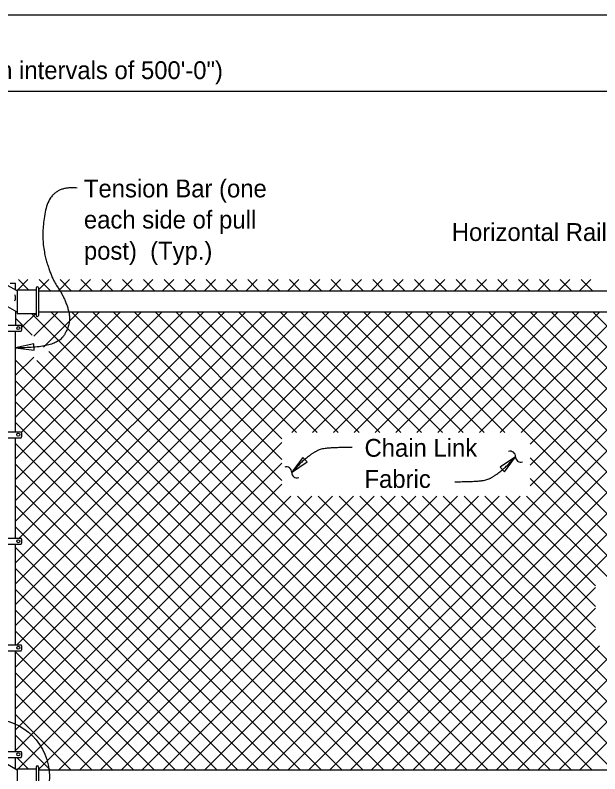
# Model space of a CAD drawing. Extents: x 110698 to 110915, y 110390 to 110472.
# Drawn here: x 110786.41 to 110793.02, y 110456.22 to 110464.8 of the extents above; entities that cross this region are included whole.
import ezdxf

# ---------------------------------------------------------------- set-up
doc = ezdxf.new("R2010")
doc.units = 0
for name, color, linetype in [('ActivePts-ConstElements', 7, 'Continuous'), ('Border', 7, 'Continuous'), ('PlotBorder_dp', 7, 'Continuous'), ('SheetBorder_dp', 7, 'Continuous'), ('TextMisc', 7, 'Continuous')]:
    doc.layers.add(name, color=color, linetype=linetype)

msp = doc.modelspace()

# ---------------------------------------------------------------- linework, layer by layer
at = {"layer": 'ActivePts-ConstElements'}
msp.add_lwpolyline([(110774.0658, 110438.856), (110815.1163, 110438.856), (110815.1163, 110464.8021), (110774.0658, 110464.8021)], close=True, dxfattribs=at)
at = {"layer": 'PlotBorder_dp'}
msp.add_line((110776.1407, 110463.9443), (110796.1408, 110463.9443), dxfattribs=at)
for points in [[(110786.4116, 110461.0428), (110786.6211, 110461.0159), (110786.6183, 110461.0864)], [(110789.5343, 110459.633), (110789.7096, 110459.7509), (110789.661, 110459.802)], [(110792.0665, 110459.8091), (110791.8912, 110459.6912), (110791.9398, 110459.64)]]:
    msp.add_lwpolyline(points, close=True, dxfattribs=at)
msp.add_circle((110786.1422, 110456.193), 0.6527, dxfattribs=at)
for centre, start, end in [((110792.0064, 110459.8118), 357.71778, 109.44499), ((110792.1255, 110459.8071), 177.71778, 289.44499), ((110789.4752, 110459.6349), 357.71778, 109.44499), ((110789.5944, 110459.6301), 177.71778, 289.44499)]:
    msp.add_arc(centre, 0.0596, start, end, dxfattribs=at)
for points in [[(110787.1072, 110462.8473), (110786.8071, 110462.8793), (110786.6917, 110462.297), (110786.8068, 110461.8427), (110786.9704, 110461.6076), (110787.0496, 110461.3212), (110786.8632, 110461.0324), (110786.4116, 110461.0428)], [(110790.2195, 110459.9146), (110789.9294, 110459.9146), (110789.7928, 110459.8698), (110789.6058, 110459.7162), (110789.5674, 110459.6586)], [(110791.3812, 110459.5273), (110791.6714, 110459.5273), (110791.808, 110459.5721), (110791.995, 110459.7257), (110792.0333, 110459.7833)]]:
    msp.add_open_spline(points, degree=2, dxfattribs=at)
at = {"layer": 'SheetBorder_dp'}
for p, q in [((110786.437, 110461.6985), (110786.5518, 110461.8133)), ((110786.4443, 110461.8133), (110786.5591, 110461.6985)), ((110786.6701, 110461.6959), (110786.7875, 110461.8133)), ((110786.68, 110461.8133), (110786.8102, 110461.6831)), ((110786.893, 110461.6831), (110787.0232, 110461.8133)), ((110786.9157, 110461.8133), (110787.0459, 110461.6831)), ((110787.1287, 110461.6831), (110787.2589, 110461.8133)), ((110787.1514, 110461.8133), (110787.2816, 110461.6831)), ((110787.3644, 110461.6831), (110787.4946, 110461.8133)), ((110787.3871, 110461.8133), (110787.5173, 110461.6831)), ((110787.6001, 110461.6831), (110787.7303, 110461.8133)), ((110787.6228, 110461.8133), (110787.753, 110461.6831)), ((110787.8358, 110461.6831), (110787.966, 110461.8133)), ((110787.8585, 110461.8133), (110787.9887, 110461.6831)), ((110788.0715, 110461.6831), (110788.2017, 110461.8133)), ((110788.0942, 110461.8133), (110788.2244, 110461.6831)), ((110788.3072, 110461.6831), (110788.4374, 110461.8133)), ((110788.3299, 110461.8133), (110788.4601, 110461.6831)), ((110788.5429, 110461.6831), (110788.6731, 110461.8133)), ((110788.5656, 110461.8133), (110788.6958, 110461.6831)), ((110788.7786, 110461.6831), (110788.9088, 110461.8133)), ((110788.8013, 110461.8133), (110788.9315, 110461.6831)), ((110789.0143, 110461.6831), (110789.1445, 110461.8133)), ((110789.0371, 110461.8133), (110789.1672, 110461.6831)), ((110789.25, 110461.6831), (110789.3802, 110461.8133)), ((110789.2728, 110461.8133), (110789.4029, 110461.6831)), ((110789.4857, 110461.6831), (110789.6159, 110461.8133)), ((110789.5085, 110461.8133), (110789.6386, 110461.6831)), ((110789.7214, 110461.6831), (110789.8516, 110461.8133)), ((110789.7442, 110461.8133), (110789.8743, 110461.6831)), ((110789.9571, 110461.6831), (110790.0873, 110461.8133)), ((110789.9799, 110461.8133), (110790.11, 110461.6831)), ((110790.1928, 110461.6831), (110790.323, 110461.8133)), ((110790.2156, 110461.8133), (110790.3457, 110461.6831)), ((110790.4285, 110461.6831), (110790.5587, 110461.8133)), ((110790.4513, 110461.8133), (110790.5814, 110461.6831)), ((110790.6642, 110461.6831), (110790.7944, 110461.8133)), ((110790.687, 110461.8133), (110790.8171, 110461.6831)), ((110790.8999, 110461.6831), (110791.0301, 110461.8133)), ((110790.9227, 110461.8133), (110791.0528, 110461.6831)), ((110791.1356, 110461.6831), (110791.2658, 110461.8133)), ((110791.1584, 110461.8133), (110791.2885, 110461.6831)), ((110791.3714, 110461.6831), (110791.5015, 110461.8133)), ((110791.3941, 110461.8133), (110791.5242, 110461.6831)), ((110791.6071, 110461.6831), (110791.7372, 110461.8133)), ((110791.6298, 110461.8133), (110791.7599, 110461.6831)), ((110791.8428, 110461.6831), (110791.9729, 110461.8133)), ((110791.8655, 110461.8133), (110791.9956, 110461.6831)), ((110792.0785, 110461.6831), (110792.2086, 110461.8133)), ((110792.1012, 110461.8133), (110792.2313, 110461.6831)), ((110792.3142, 110461.6831), (110792.4443, 110461.8133)), ((110792.3369, 110461.8133), (110792.467, 110461.6831)), ((110792.5499, 110461.6831), (110792.68, 110461.8133)), ((110792.5726, 110461.8133), (110792.7028, 110461.6831)), ((110792.7856, 110461.6831), (110792.9157, 110461.8133)), ((110792.8083, 110461.8133), (110792.9385, 110461.6831)), ((110786.4116, 110458.3733), (110789.4819, 110461.4435)), ((110786.4116, 110457.9019), (110789.9533, 110461.4435)), ((110786.4116, 110459.7875), (110788.0676, 110461.4435)), ((110786.4116, 110459.3161), (110788.539, 110461.4435)), ((110786.4116, 110460.2589), (110787.5962, 110461.4435)), ((110786.4116, 110458.1376), (110789.7176, 110461.4435)), ((110786.4116, 110458.609), (110789.2461, 110461.4435)), ((110786.4116, 110459.0804), (110788.7747, 110461.4435)), ((110786.4116, 110459.5518), (110788.3033, 110461.4435)), ((110786.4116, 110457.1948), (110790.6604, 110461.4435)), ((110786.4116, 110457.4305), (110790.4247, 110461.4435)), ((110786.4116, 110460.4946), (110787.3605, 110461.4435)), ((110786.4279, 110457.6825), (110790.189, 110461.4435)), ((110786.4543, 110458.8873), (110789.0104, 110461.4435)), ((110786.4775, 110460.0891), (110787.8319, 110461.4435)), ((110786.4835, 110461.2736), (110786.6433, 110461.4334)), ((110786.5956, 110461.4263), (110791.7555, 110456.2664)), ((110786.6182, 110461.1725), (110786.8891, 110461.4435)), ((110786.729, 110461.0477), (110787.1248, 110461.4435)), ((110786.8141, 110461.4435), (110791.9912, 110456.2664)), ((110787.0498, 110461.4435), (110792.2269, 110456.2664)), ((110787.2855, 110461.4435), (110792.4626, 110456.2664)), ((110787.5212, 110461.4435), (110789.4233, 110459.5414)), ((110787.7569, 110461.4435), (110789.4233, 110459.7771)), ((110787.9926, 110461.4435), (110789.4233, 110460.0128)), ((110788.2283, 110461.4435), (110789.5888, 110460.083)), ((110788.464, 110461.4435), (110789.8245, 110460.083)), ((110788.6997, 110461.4435), (110790.0602, 110460.083)), ((110788.9354, 110461.4435), (110790.2959, 110460.083)), ((110789.1711, 110461.4435), (110790.5316, 110460.083)), ((110789.2545, 110456.2664), (110794.4316, 110461.4435)), ((110789.4068, 110461.4435), (110790.7673, 110460.083)), ((110789.4902, 110456.2664), (110794.6673, 110461.4435)), ((110789.5356, 110460.083), (110790.8961, 110461.4435)), ((110789.6425, 110461.4435), (110791.003, 110460.083)), ((110789.7259, 110456.2664), (110794.903, 110461.4435)), ((110789.7713, 110460.083), (110791.1318, 110461.4435)), ((110789.8782, 110461.4435), (110791.2387, 110460.083)), ((110789.9616, 110456.2664), (110795.1387, 110461.4435)), ((110790.007, 110460.083), (110791.3675, 110461.4435)), ((110790.1139, 110461.4435), (110791.4744, 110460.083)), ((110790.1973, 110456.2664), (110795.3744, 110461.4435)), ((110790.2427, 110460.083), (110791.6032, 110461.4435)), ((110790.3496, 110461.4435), (110791.7101, 110460.083)), ((110790.433, 110456.2664), (110795.6114, 110461.4448)), ((110790.4784, 110460.083), (110791.8389, 110461.4435)), ((110790.5853, 110461.4435), (110791.9458, 110460.083)), ((110790.6687, 110456.2664), (110795.8286, 110461.4263)), ((110790.7141, 110460.083), (110792.0746, 110461.4435)), ((110790.821, 110461.4435), (110793.8469, 110458.4176)), ((110790.9498, 110460.083), (110792.3103, 110461.4435)), ((110791.0567, 110461.4435), (110794.0826, 110458.4176)), ((110791.1855, 110460.083), (110792.546, 110461.4435)), ((110791.2924, 110461.4435), (110794.3183, 110458.4176)), ((110791.4212, 110460.083), (110792.7817, 110461.4435)), ((110791.5281, 110461.4435), (110794.554, 110458.4176)), ((110791.6569, 110460.083), (110793.0174, 110461.4435)), ((110791.7638, 110461.4435), (110794.7897, 110458.4176)), ((110791.8926, 110460.083), (110793.2531, 110461.4435)), ((110791.9995, 110461.4435), (110795.0254, 110458.4176)), ((110792.1283, 110460.083), (110793.4888, 110461.4435)), ((110792.2315, 110459.9505), (110793.7245, 110461.4435)), ((110792.2315, 110459.4791), (110794.1959, 110461.4435)), ((110792.2315, 110459.7148), (110793.9602, 110461.4435)), ((110792.2352, 110461.4435), (110795.2611, 110458.4176)), ((110792.4709, 110461.4435), (110795.4968, 110458.4176)), ((110792.7066, 110461.4435), (110795.7325, 110458.4176)), ((110792.9423, 110461.4435), (110795.995, 110458.3909)), ((110786.4116, 110461.3745), (110786.6002, 110461.186)), ((110786.7882, 110460.9979), (110791.5198, 110456.2664)), ((110786.4116, 110460.7303), (110786.6184, 110460.9371)), ((110786.4116, 110460.9031), (110791.0484, 110456.2664)), ((110786.6513, 110460.8992), (110791.2841, 110456.2664)), ((110786.4116, 110460.6674), (110790.8127, 110456.2664)), ((110786.4116, 110460.4317), (110790.577, 110456.2664)), ((110786.4116, 110460.196), (110790.3413, 110456.2664)), ((110786.4116, 110456.9591), (110789.4233, 110459.9708)), ((110786.4116, 110459.9603), (110790.1056, 110456.2664)), ((110792.2315, 110459.7974), (110793.6112, 110458.4176)), ((110786.4116, 110456.7234), (110789.4233, 110459.7351)), ((110786.4116, 110459.7246), (110789.8699, 110456.2664)), ((110792.2315, 110459.5617), (110793.3755, 110458.4176)), ((110786.4116, 110456.4877), (110789.4233, 110459.4994)), ((110786.4116, 110459.4889), (110789.6342, 110456.2664)), ((110786.4415, 110456.2818), (110789.5253, 110459.3656)), ((110786.6701, 110456.2748), (110789.761, 110459.3656)), ((110786.8974, 110456.2664), (110789.9967, 110459.3656)), ((110787.1331, 110456.2664), (110790.2324, 110459.3656)), ((110787.3688, 110456.2664), (110790.4681, 110459.3656)), ((110787.6045, 110456.2664), (110790.7038, 110459.3656)), ((110787.8403, 110456.2664), (110790.9395, 110459.3656)), ((110788.076, 110456.2664), (110791.1752, 110459.3656)), ((110788.3117, 110456.2664), (110791.4109, 110459.3656)), ((110788.5474, 110456.2664), (110791.6466, 110459.3656)), ((110788.7831, 110456.2664), (110791.8823, 110459.3656)), ((110789.0188, 110456.2664), (110792.118, 110459.3656)), ((110789.5991, 110459.3656), (110792.6983, 110456.2664)), ((110789.8348, 110459.3656), (110792.934, 110456.2664)), ((110790.0705, 110459.3656), (110793.1697, 110456.2664)), ((110790.3062, 110459.3656), (110793.4054, 110456.2664)), ((110790.5419, 110459.3656), (110793.6411, 110456.2664)), ((110790.7776, 110459.3656), (110793.8768, 110456.2664)), ((110791.0133, 110459.3656), (110794.1125, 110456.2664)), ((110791.249, 110459.3656), (110794.3482, 110456.2664)), ((110791.4847, 110459.3656), (110792.97, 110457.8803)), ((110791.7204, 110459.3656), (110792.97, 110458.116)), ((110791.9561, 110459.3656), (110792.97, 110458.3517)), ((110792.1918, 110459.3656), (110793.1398, 110458.4176)), ((110786.4116, 110459.2532), (110789.3985, 110456.2664)), ((110786.4116, 110459.0175), (110789.1628, 110456.2664)), ((110786.4116, 110458.7818), (110788.9271, 110456.2664)), ((110786.4116, 110458.5461), (110788.6914, 110456.2664)), ((110786.4116, 110458.3104), (110788.4557, 110456.2664)), ((110790.9044, 110456.2664), (110792.97, 110458.332)), ((110791.1401, 110456.2664), (110792.97, 110458.0963)), ((110786.4116, 110458.0747), (110788.22, 110456.2664)), ((110786.4116, 110457.839), (110787.9843, 110456.2664)), ((110791.3758, 110456.2664), (110792.97, 110457.8606)), ((110791.6115, 110456.2664), (110793.0172, 110457.6721)), ((110791.8472, 110456.2664), (110793.2529, 110457.6721)), ((110792.0829, 110456.2664), (110793.4886, 110457.6721)), ((110792.3186, 110456.2664), (110793.7243, 110457.6721)), ((110792.5543, 110456.2664), (110793.96, 110457.6721)), ((110792.79, 110456.2664), (110794.1957, 110457.6721)), ((110786.4116, 110457.6033), (110787.7486, 110456.2664)), ((110786.4116, 110457.3676), (110787.5129, 110456.2664)), ((110786.4116, 110457.1319), (110787.2772, 110456.2664)), ((110786.4116, 110456.8962), (110787.0415, 110456.2664)), ((110786.4116, 110456.6605), (110786.8058, 110456.2664)), ((110786.4262, 110456.4102), (110786.5546, 110456.2818))]:
    msp.add_line(p, q, dxfattribs=at)
at = {"layer": 'TextMisc'}
for p, q in [((110786.3491, 110461.7716), (110786.4116, 110461.7716)), ((110786.4116, 110461.6941), (110786.4116, 110461.7716)), ((110786.4303, 110461.6838), (110786.3195, 110461.7452)), ((110786.4303, 110461.6985), (110786.4303, 110461.4263)), ((110786.4303, 110461.6985), (110786.6433, 110461.6985)), ((110786.6433, 110461.7181), (110786.6433, 110461.4084)), ((110786.6701, 110461.7181), (110786.6701, 110461.4084)), ((110795.6114, 110461.6831), (110786.6701, 110461.6831)), ((110786.4303, 110461.4444), (110786.2164, 110461.563)), ((110786.4116, 110461.4548), (110786.4116, 110461.2967)), ((110786.4116, 110461.4548), (110786.4116, 110461.4425)), ((110786.6433, 110461.4263), (110786.4303, 110461.4263)), ((110795.6114, 110461.4435), (110786.6701, 110461.4435)), ((110785.9851, 110461.2967), (110786.4761, 110461.2967)), ((110785.9851, 110461.2291), (110786.4754, 110461.2291)), ((110786.4116, 110460.092), (110786.4116, 110461.2291)), ((110785.9851, 110460.092), (110786.4761, 110460.092)), ((110785.9851, 110460.0244), (110786.4754, 110460.0244)), ((110786.4116, 110458.8873), (110786.4116, 110460.0244)), ((110785.9851, 110458.8873), (110786.4761, 110458.8873)), ((110785.9851, 110458.8197), (110786.4754, 110458.8197)), ((110786.4116, 110457.6825), (110786.4116, 110458.8197)), ((110785.9851, 110457.6825), (110786.4761, 110457.6825)), ((110785.9851, 110457.6149), (110786.4754, 110457.6149)), ((110786.4116, 110456.4779), (110786.4116, 110457.6149)), ((110785.9851, 110456.4779), (110786.4761, 110456.4779)), ((110785.9851, 110456.4102), (110786.4754, 110456.4102)), ((110786.4116, 110456.2774), (110786.4116, 110456.4102)), ((110786.4303, 110456.2671), (110786.3195, 110456.3284)), ((110786.4303, 110456.2818), (110786.4303, 110456.0096)), ((110786.4303, 110456.2818), (110786.6433, 110456.2818)), ((110786.6433, 110456.3014), (110786.6433, 110455.9917)), ((110786.6701, 110456.3014), (110786.6701, 110455.9917)), ((110795.6114, 110456.2664), (110786.6701, 110456.2664))]:
    msp.add_line(p, q, dxfattribs=at)
for centre, start, end in [((110786.6566, 110461.718), 0, 180), ((110786.6566, 110461.4082), 180, 0), ((110786.6566, 110456.3013), 0, 180)]:
    msp.add_arc(centre, 0.0134, start, end, dxfattribs=at)
for centre, start_param, end_param in [((110786.334, 110461.6072), 5.810211, 6.75616), ((110786.4066, 110461.2636), 5.801244, 6.745158), ((110786.4066, 110460.0589), 5.801046, 6.744962), ((110786.4066, 110460.0589), 5.801046, 6.744962), ((110786.4066, 110458.8542), 5.800848, 6.744767), ((110786.4066, 110458.8542), 5.800848, 6.744767), ((110786.4066, 110457.6493), 5.810211, 6.745158), ((110786.4066, 110457.6493), 5.810211, 6.745158), ((110786.4066, 110456.4447), 5.800651, 6.745353)]:
    msp.add_ellipse(centre, major_axis=(0.0776, 0), ratio=0.957868, start_param=start_param, end_param=end_param, dxfattribs=at)
for centre in [(110786.4424, 110461.264), (110786.4424, 110460.0593), (110786.4424, 110460.0593), (110786.4424, 110458.8546), (110786.4424, 110458.8546), (110786.4424, 110457.6497), (110786.4424, 110457.6497), (110786.4424, 110456.4451)]:
    msp.add_ellipse(centre, major_axis=(-0.0177, 0), ratio=0.957868, dxfattribs=at)

# ---------------------------------------------------------------- texts
at = {"layer": 'Border'}
for s, p in [('Pull Post Assembly (required at maximum intervals of 500\'-0")', (110781.3729, 110464.0792)), ('Horizontal Rail', (110791.3454, 110462.2491))]:
    msp.add_text(s, height=0.2016, dxfattribs=at).set_placement(p)
at = {"layer": 'PlotBorder_dp'}
for s, p in [('Tension Bar (one ', (110787.1848, 110462.742)), ('each side of pull ', (110787.1848, 110462.39)), ('post)  (Typ.)', (110787.1848, 110462.038)), ('Chain Link ', (110790.3583, 110459.8094)), ('Fabric ', (110790.3583, 110459.4574))]:
    msp.add_text(s, height=0.2016, dxfattribs=at).set_placement(p)

doc.saveas('drawing.dxf')
